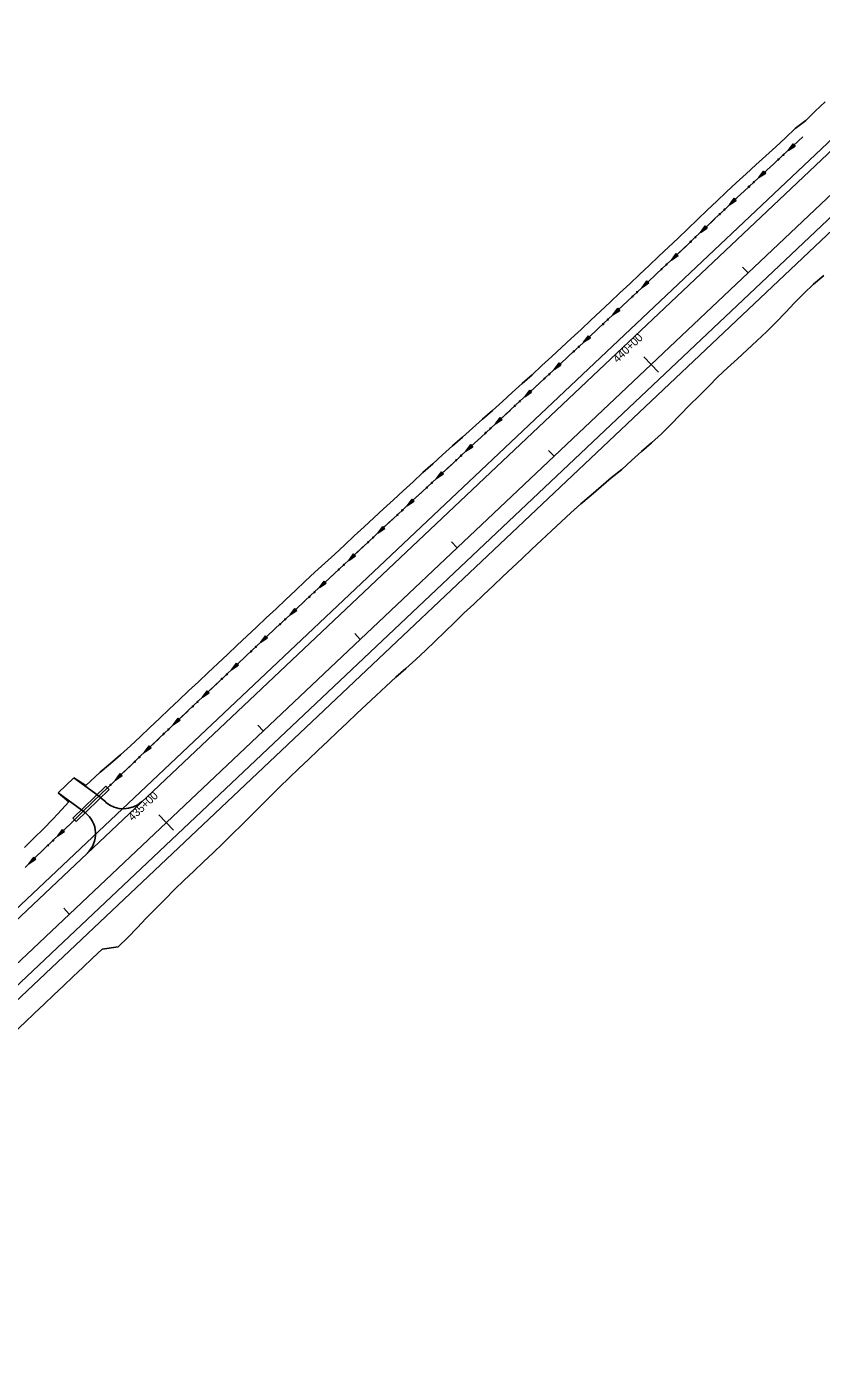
# Model space of a CAD drawing. Extents: x 1375694 to 1433473, y 1931050 to 1967991.
# Drawn here: x 1431005 to 1431601, y 1965367 to 1966371 of the extents above; entities that cross this region are included whole.
import ezdxf

# ---------------------------------------------------------------- set-up
doc = ezdxf.new("R2010")
doc.units = 0
for name, color, linetype in [('62', 7, 'Continuous'), ('R_Drainage', 7, 'Continuous'), ('R_Horz Alg', 7, 'Continuous'), ('R_Horz Alg Annot', 7, 'Continuous'), ('R_Proposed Const Limits', 7, 'Continuous'), ('R_Proposed Road', 7, 'Continuous')]:
    doc.layers.add(name, color=color, linetype=linetype)

msp = doc.modelspace()

# ---------------------------------------------------------------- linework, layer by layer
at = {"layer": '62'}
for p, q in [((1431579.8, 1966283.2), (1431576.1, 1966278.3)), ((1431576.1, 1966278.3), (1431581.2, 1966281.6)), ((1431581.2, 1966281.6), (1431579.8, 1966283.2)), ((1431557.7, 1966262.7), (1431554.1, 1966257.9)), ((1431554.1, 1966257.9), (1431559.2, 1966261.2)), ((1431559.2, 1966261.2), (1431557.7, 1966262.7)), ((1431535.7, 1966242.4), (1431532, 1966237.5)), ((1431532, 1966237.5), (1431537.1, 1966240.8)), ((1431537.1, 1966240.8), (1431535.7, 1966242.4)), ((1431513.9, 1966221.7), (1431510.3, 1966216.8)), ((1431510.3, 1966216.8), (1431515.3, 1966220.1)), ((1431515.3, 1966220.1), (1431513.9, 1966221.7)), ((1431492.1, 1966201), (1431488.5, 1966196.1)), ((1431488.5, 1966196.1), (1431493.6, 1966199.4)), ((1431493.6, 1966199.4), (1431492.1, 1966201)), ((1431470.2, 1966180.4), (1431466.6, 1966175.5)), ((1431466.6, 1966175.5), (1431471.7, 1966178.9)), ((1431471.7, 1966178.9), (1431470.2, 1966180.4)), ((1431448.3, 1966159.9), (1431444.7, 1966155)), ((1431444.7, 1966155), (1431449.8, 1966158.3)), ((1431449.8, 1966158.3), (1431448.3, 1966159.9)), ((1431426.4, 1966139.3), (1431422.7, 1966134.5)), ((1431422.7, 1966134.5), (1431427.8, 1966137.8)), ((1431427.8, 1966137.8), (1431426.4, 1966139.3)), ((1431404.4, 1966118.9), (1431400.7, 1966114)), ((1431400.7, 1966114), (1431405.8, 1966117.3)), ((1431405.8, 1966117.3), (1431404.4, 1966118.9)), ((1431382.4, 1966098.5), (1431378.7, 1966093.6)), ((1431378.7, 1966093.6), (1431383.8, 1966096.9)), ((1431383.8, 1966096.9), (1431382.4, 1966098.5)), ((1431360.3, 1966078.1), (1431356.6, 1966073.2)), ((1431356.6, 1966073.2), (1431361.7, 1966076.5)), ((1431361.7, 1966076.5), (1431360.3, 1966078.1)), ((1431338.2, 1966057.7), (1431334.6, 1966052.8)), ((1431334.6, 1966052.8), (1431339.7, 1966056.1)), ((1431339.7, 1966056.1), (1431338.2, 1966057.7)), ((1431316.2, 1966037.2), (1431312.6, 1966032.4)), ((1431312.6, 1966032.4), (1431317.7, 1966035.7)), ((1431317.7, 1966035.7), (1431316.2, 1966037.2)), ((1431294.2, 1966016.8), (1431290.6, 1966011.9)), ((1431295.7, 1966015.2), (1431294.2, 1966016.8)), ((1431290.6, 1966011.9), (1431295.7, 1966015.2)), ((1431272.3, 1965996.3), (1431268.6, 1965991.4)), ((1431273.7, 1965994.8), (1431272.3, 1965996.3)), ((1431268.6, 1965991.4), (1431273.7, 1965994.8)), ((1431250.3, 1965975.8), (1431246.7, 1965970.9)), ((1431251.8, 1965974.2), (1431250.3, 1965975.8)), ((1431246.7, 1965970.9), (1431251.8, 1965974.2)), ((1431228.3, 1965955.3), (1431224.7, 1965950.5)), ((1431229.8, 1965953.8), (1431228.3, 1965955.3)), ((1431224.7, 1965950.5), (1431229.8, 1965953.8)), ((1431206.3, 1965934.9), (1431202.7, 1965930)), ((1431202.7, 1965930), (1431207.8, 1965933.3)), ((1431207.8, 1965933.3), (1431206.3, 1965934.9)), ((1431184.4, 1965914.3), (1431180.8, 1965909.5)), ((1431180.8, 1965909.5), (1431185.9, 1965912.8)), ((1431185.9, 1965912.8), (1431184.4, 1965914.3)), ((1431162.5, 1965893.8), (1431158.9, 1965888.9)), ((1431158.9, 1965888.9), (1431164, 1965892.2)), ((1431164, 1965892.2), (1431162.5, 1965893.8)), ((1431140.7, 1965873.2), (1431137, 1965868.3)), ((1431137, 1965868.3), (1431142.1, 1965871.6)), ((1431142.1, 1965871.6), (1431140.7, 1965873.2)), ((1431118.9, 1965852.5), (1431115.2, 1965847.6)), ((1431115.2, 1965847.6), (1431120.3, 1965851)), ((1431120.3, 1965851), (1431118.9, 1965852.5)), ((1431097.1, 1965831.8), (1431093.5, 1965826.9)), ((1431093.5, 1965826.9), (1431098.6, 1965830.3)), ((1431098.6, 1965830.3), (1431097.1, 1965831.8)), ((1431075.4, 1965811), (1431071.8, 1965806.1)), ((1431071.8, 1965806.1), (1431076.9, 1965809.5)), ((1431076.9, 1965809.5), (1431075.4, 1965811)), ((1431032.2, 1965769.2), (1431028.7, 1965764.3)), ((1431028.7, 1965764.3), (1431033.7, 1965767.7)), ((1431033.7, 1965767.7), (1431032.2, 1965769.2)), ((1431010.6, 1965748.4), (1431007, 1965743.4)), ((1431007, 1965743.4), (1431012.1, 1965746.8)), ((1431012.1, 1965746.8), (1431010.6, 1965748.4))]:
    msp.add_line(p, q, dxfattribs=at)
for points in [[(1431004.1, 1965740.6), (1431011.3, 1965747.6), (1431018.5, 1965754.5), (1431025.7, 1965761.5), (1431032.9, 1965768.4), (1431040.1, 1965775.4), (1431047.3, 1965782.4), (1431054.4, 1965789.3), (1431061.6, 1965796.3), (1431068.8, 1965803.2), (1431076, 1965810.1), (1431083.3, 1965817.1), (1431090.5, 1965824), (1431097.7, 1965830.9), (1431104.9, 1965837.8), (1431112.2, 1965844.7), (1431119.4, 1965851.6), (1431126.7, 1965858.5), (1431133.9, 1965865.4), (1431141.2, 1965872.2), (1431148.5, 1965879.1), (1431155.7, 1965885.9), (1431163, 1965892.8), (1431170.3, 1965899.7), (1431177.6, 1965906.5), (1431184.9, 1965913.3), (1431192.2, 1965920.2), (1431199.5, 1965927), (1431206.8, 1965933.9), (1431214.1, 1965940.7), (1431221.4, 1965947.5), (1431228.8, 1965954.3), (1431236.1, 1965961.1), (1431243.4, 1965967.9), (1431250.7, 1965974.7), (1431258, 1965981.5), (1431265.3, 1965988.4), (1431272.6, 1965995.2), (1431279.9, 1966002), (1431287.3, 1966008.8), (1431294.6, 1966015.7), (1431301.9, 1966022.5), (1431309.2, 1966029.3), (1431316.5, 1966036.1), (1431323.9, 1966042.9), (1431331.2, 1966049.7), (1431338.5, 1966056.5), (1431345.9, 1966063.3), (1431353.2, 1966070.1), (1431360.5, 1966076.9), (1431367.9, 1966083.7), (1431375.2, 1966090.5), (1431382.6, 1966097.3), (1431389.9, 1966104), (1431397.3, 1966110.8), (1431404.6, 1966117.6), (1431411.9, 1966124.4), (1431419.3, 1966131.2), (1431426.6, 1966138.1), (1431433.9, 1966144.9), (1431441.2, 1966151.7), (1431448.5, 1966158.6), (1431455.8, 1966165.4), (1431463.1, 1966172.2), (1431470.3, 1966179.1), (1431477.6, 1966185.9), (1431484.9, 1966192.8), (1431492.2, 1966199.6), (1431499.5, 1966206.5), (1431506.7, 1966213.4), (1431514, 1966220.3), (1431521.2, 1966227.2), (1431528.5, 1966234.1), (1431535.7, 1966240.9), (1431543.1, 1966247.7), (1431550.4, 1966254.5), (1431557.7, 1966261.3), (1431565.1, 1966268.1), (1431572.4, 1966274.9), (1431579.8, 1966281.7), (1431587.1, 1966288.5)], [(1431587.1, 1966288.5), (1431579.8, 1966281.7), (1431576.1, 1966278.3)], [(1431565.1, 1966268.1), (1431557.7, 1966261.3), (1431554.1, 1966257.9)], [(1431565.1, 1966268.1), (1431565.1, 1966268.1), (1431565.1, 1966268.1)], [(1431543, 1966247.7), (1431535.7, 1966240.9), (1431532, 1966237.5)], [(1431543, 1966247.7), (1431543, 1966247.7)], [(1431521.1, 1966227.1), (1431514, 1966220.3), (1431510.3, 1966216.8)], [(1431521.2, 1966227.1), (1431521.1, 1966227.1)], [(1431499.4, 1966206.4), (1431492.2, 1966199.6), (1431488.5, 1966196.1)], [(1431499.4, 1966206.4), (1431499.4, 1966206.4)], [(1431477.5, 1966185.8), (1431470.3, 1966179.1), (1431466.6, 1966175.5)], [(1431477.5, 1966185.8), (1431477.5, 1966185.8)], [(1431455.6, 1966165.3), (1431448.5, 1966158.6), (1431444.7, 1966155)], [(1431455.6, 1966165.3), (1431455.6, 1966165.3)], [(1431433.7, 1966144.7), (1431426.6, 1966138.1), (1431422.7, 1966134.5)], [(1431433.7, 1966144.7), (1431433.7, 1966144.7)], [(1431411.7, 1966124.2), (1431404.6, 1966117.6), (1431400.7, 1966114)], [(1431411.7, 1966124.3), (1431411.7, 1966124.2)], [(1431389.7, 1966103.8), (1431382.6, 1966097.3), (1431378.7, 1966093.6)], [(1431389.7, 1966103.8), (1431389.7, 1966103.8)], [(1431367.6, 1966083.4), (1431360.5, 1966076.9), (1431356.6, 1966073.2)], [(1431367.6, 1966083.5), (1431367.6, 1966083.4)], [(1431345.6, 1966063), (1431338.5, 1966056.5), (1431334.6, 1966052.8)], [(1431345.6, 1966063.1), (1431345.6, 1966063)], [(1431323.6, 1966042.6), (1431316.5, 1966036.1), (1431312.6, 1966032.4)], [(1431323.6, 1966042.6), (1431323.6, 1966042.6)], [(1431301.5, 1966022.1), (1431294.6, 1966015.7), (1431290.6, 1966011.9)], [(1431301.6, 1966022.2), (1431301.5, 1966022.1)], [(1431279.6, 1966001.7), (1431272.6, 1965995.2), (1431268.6, 1965991.4)], [(1431279.6, 1966001.7), (1431279.6, 1966001.7)], [(1431257.6, 1965981.2), (1431250.7, 1965974.7), (1431246.7, 1965970.9)], [(1431257.6, 1965981.2), (1431257.6, 1965981.2)], [(1431235.7, 1965960.7), (1431228.8, 1965954.3), (1431224.7, 1965950.5)], [(1431235.7, 1965960.7), (1431235.7, 1965960.7)], [(1431213.6, 1965940.2), (1431206.8, 1965933.9), (1431202.7, 1965930)], [(1431213.7, 1965940.3), (1431213.6, 1965940.2)], [(1431191.7, 1965919.7), (1431184.9, 1965913.3), (1431180.8, 1965909.5)], [(1431191.7, 1965919.8), (1431191.7, 1965919.7)], [(1431169.8, 1965899.2), (1431163, 1965892.8), (1431158.9, 1965888.9)], [(1431169.8, 1965899.2), (1431169.8, 1965899.2)], [(1431147.9, 1965878.6), (1431141.2, 1965872.2), (1431137, 1965868.3)], [(1431148, 1965878.6), (1431147.9, 1965878.6)], [(1431126.1, 1965857.9), (1431119.4, 1965851.6), (1431115.2, 1965847.6)], [(1431126.1, 1965858), (1431126.1, 1965857.9)], [(1431104.3, 1965837.2), (1431097.7, 1965830.9), (1431093.5, 1965826.9)], [(1431104.4, 1965837.3), (1431104.3, 1965837.2)], [(1431082.6, 1965816.5), (1431076, 1965810.1), (1431071.8, 1965806.1)], [(1431082.7, 1965816.5), (1431082.6, 1965816.5)], [(1431039.4, 1965774.7), (1431032.9, 1965768.4), (1431028.7, 1965764.3)], [(1431039.4, 1965774.8), (1431039.4, 1965774.7)], [(1431017.8, 1965753.8), (1431011.3, 1965747.6), (1431007, 1965743.4)], [(1431017.9, 1965753.9), (1431017.8, 1965753.8)]]:
    msp.add_lwpolyline(points, dxfattribs=at)
for centre in [(1431568.8, 1966271.5), (1431572.5, 1966274.9), (1431546.7, 1966251.1), (1431550.4, 1966254.5), (1431524.8, 1966230.5), (1431528.4, 1966234), (1431503, 1966209.8), (1431506.7, 1966213.3), (1431481.2, 1966189.2), (1431484.8, 1966192.7), (1431459.3, 1966168.7), (1431462.9, 1966172.1), (1431437.4, 1966148.1), (1431441, 1966151.5), (1431415.4, 1966127.6), (1431419.1, 1966131), (1431393.4, 1966107.2), (1431397.1, 1966110.6), (1431371.3, 1966086.8), (1431375, 1966090.2), (1431349.3, 1966066.4), (1431352.9, 1966069.8), (1431327.3, 1966046), (1431330.9, 1966049.4), (1431305.3, 1966025.5), (1431308.9, 1966029), (1431283.3, 1966005.1), (1431286.9, 1966008.5), (1431265, 1965988), (1431261.3, 1965984.6), (1431243, 1965967.5), (1431239.4, 1965964.1), (1431221, 1965947), (1431217.3, 1965943.6), (1431199, 1965926.6), (1431195.4, 1965923.1), (1431177.1, 1965906), (1431173.5, 1965902.6), (1431155.3, 1965885.4), (1431151.6, 1965882), (1431133.4, 1965864.8), (1431129.8, 1965861.4), (1431108, 1965840.7), (1431111.6, 1965844.1), (1431086.3, 1965819.9), (1431089.9, 1965823.4), (1431068.2, 1965802.6), (1431021.5, 1965757.3), (1431025.1, 1965760.8)]:
    msp.add_circle(centre, 0.375, dxfattribs=at)
at = {"layer": 'R_Drainage'}
for p, q in [((1431064.6, 1965801.6), (1431040, 1965777.7)), ((1431042.4, 1965775.2), (1431067.1, 1965799.1)), ((1431067.1, 1965799.1), (1431064.6, 1965801.6)), ((1431040, 1965777.7), (1431042.4, 1965775.2))]:
    msp.add_line(p, q, dxfattribs=at)
at = {"layer": 'R_Horz Alg'}
msp.add_line((1430431.8, 1965133.5), (1432780.4, 1967352.8), dxfattribs=at)
at = {"layer": 'R_Horz Alg Annot'}
for points in [[(1431541.9, 1966190.7), (1431546, 1966186.4)], [(1431467.8, 1966123.5), (1431478.8, 1966111.9)], [(1431396.5, 1966053.4), (1431400.7, 1966049)], [(1431323.8, 1965984.7), (1431328, 1965980.3)], [(1431251.2, 1965916), (1431255.3, 1965911.6)], [(1431178.5, 1965847.3), (1431182.6, 1965843)], [(1431104.4, 1965780.1), (1431115.4, 1965768.5)], [(1431033.1, 1965710), (1431037.2, 1965705.6)]]:
    msp.add_lwpolyline(points, dxfattribs=at)
at = {"layer": 'R_Proposed Const Limits'}
for p, q in [((1431040.7, 1965807.8), (1431049.8, 1965802.1)), ((1431028.9, 1965796.6), (1431037, 1965789.8))]:
    msp.add_line(p, q, dxfattribs=at)
for points in [[(1431581.4, 1966294.6), (1431589.2, 1966300.8), (1431596.4, 1966307.8), (1431603.7, 1966314.6)], [(1431049.8, 1965802.1), (1431053.1, 1965805.3), (1431060.5, 1965812), (1431068.1, 1965818.6), (1431075.7, 1965825.1), (1431083.1, 1965831.8), (1431090.4, 1965838.7), (1431097.6, 1965845.5), (1431104.9, 1965852.4), (1431112.2, 1965859.3), (1431119.4, 1965866.1), (1431126.7, 1965873), (1431134, 1965879.8), (1431141.3, 1965886.7), (1431148.6, 1965893.5), (1431155.9, 1965900.4), (1431163.1, 1965907.3), (1431170.4, 1965914.1), (1431177.7, 1965920.9), (1431184.9, 1965927.8), (1431192.3, 1965934.6), (1431199.5, 1965941.6), (1431206.9, 1965948.3), (1431214.1, 1965955.2), (1431221.4, 1965962), (1431228.8, 1965968.8), (1431236.2, 1965975.6), (1431243.5, 1965982.4), (1431250.8, 1965989.2), (1431258.2, 1965996), (1431265.5, 1966002.8), (1431272.8, 1966009.6), (1431280.2, 1966016.3), (1431287.5, 1966023.1), (1431294.9, 1966029.9), (1431302.2, 1966036.7), (1431309.7, 1966043.4), (1431317.1, 1966050.1), (1431324.6, 1966056.7), (1431332, 1966063.4), (1431339.4, 1966070.1), (1431346.9, 1966076.7), (1431354.4, 1966083.4), (1431361.9, 1966090.1), (1431369.3, 1966096.7), (1431376.8, 1966103.4), (1431384.2, 1966110.1), (1431391.5, 1966116.9), (1431398.9, 1966123.7), (1431406.2, 1966130.5), (1431413.5, 1966137.3), (1431420.8, 1966144.1), (1431428.1, 1966151), (1431435.4, 1966157.8), (1431442.7, 1966164.6), (1431450, 1966171.5), (1431457.3, 1966178.3), (1431464.6, 1966185.2), (1431471.9, 1966192), (1431479.2, 1966198.9), (1431486.4, 1966205.8), (1431493.7, 1966212.6), (1431500.9, 1966219.5), (1431508.1, 1966226.4), (1431515.4, 1966233.4), (1431522.6, 1966240.3), (1431529.8, 1966247.2), (1431537.2, 1966253.9), (1431544.6, 1966260.7), (1431551.9, 1966267.5), (1431559.3, 1966274.2), (1431566.7, 1966281), (1431574, 1966287.8), (1431581.4, 1966294.6)], [(1431061.9, 1965679.5), (1431074, 1965681.2), (1431081.2, 1965688.2), (1431088.1, 1965695.4), (1431095, 1965702.7), (1431102.1, 1965709.8), (1431109.1, 1965716.9), (1431116.1, 1965724), (1431123.3, 1965731), (1431130.6, 1965737.8), (1431137.8, 1965744.8), (1431145, 1965751.7), (1431152.3, 1965758.5), (1431159.4, 1965765.6), (1431166.5, 1965772.6), (1431173.7, 1965779.6), (1431180.7, 1965786.7), (1431187.8, 1965793.8), (1431194.9, 1965800.8), (1431202, 1965807.9), (1431209.2, 1965814.8), (1431216.5, 1965821.7), (1431223.7, 1965828.5), (1431231, 1965835.4), (1431238.3, 1965842.3), (1431245.5, 1965849.2), (1431252.8, 1965856), (1431260.1, 1965862.9), (1431267.4, 1965869.7), (1431274.7, 1965876.5), (1431282.1, 1965883.2), (1431289.6, 1965889.9), (1431297, 1965896.6), (1431304.3, 1965903.4), (1431311.5, 1965910.4), (1431318.8, 1965917.3), (1431325.9, 1965924.2), (1431333.1, 1965931.2), (1431340.4, 1965938.1), (1431347.6, 1965945), (1431354.9, 1965951.8), (1431362.1, 1965958.7), (1431369.4, 1965965.6), (1431376.7, 1965972.4), (1431384, 1965979.3), (1431391.3, 1965986.1), (1431398.6, 1965993), (1431405.9, 1965999.8), (1431413.3, 1966006.5), (1431420.7, 1966013.2), (1431428.3, 1966019.7), (1431435.8, 1966026.4), (1431443.4, 1966032.9), (1431451.3, 1966039.1), (1431458.7, 1966045.8), (1431466.2, 1966052.5), (1431473.6, 1966059.1), (1431481.1, 1966065.8), (1431488.2, 1966072.9), (1431495.1, 1966080.1), (1431502.2, 1966087.2), (1431509.3, 1966094.2), (1431516.3, 1966101.3), (1431523.4, 1966108.4), (1431530.7, 1966115.2), (1431538.1, 1966122), (1431545.4, 1966128.8), (1431552.7, 1966135.6), (1431560, 1966142.5), (1431567, 1966149.6), (1431574, 1966156.8), (1431580.9, 1966164), (1431587.9, 1966171.1), (1431595.1, 1966178.1), (1431602.7, 1966184.6)], [(1431003.6, 1965755.7), (1431010.8, 1965762.7), (1431018, 1965769.7), (1431024.9, 1965776.9), (1431031.7, 1965784.2), (1431037, 1965789.8)], [(1430982.1, 1965603.8), (1430989.3, 1965610.7), (1430996.6, 1965617.6), (1431003.9, 1965624.4), (1431011.1, 1965631.3), (1431018.4, 1965638.2), (1431025.7, 1965645.1), (1431032.9, 1965651.9), (1431040.2, 1965658.8), (1431047.4, 1965665.7), (1431054.7, 1965672.6), (1431061.9, 1965679.5)]]:
    msp.add_lwpolyline(points, dxfattribs=at)
at = {"layer": 'R_Proposed Road'}
for p, q in [((1430411.1, 1965155.3), (1432759.8, 1967374.6)), ((1430415.3, 1965150.9), (1432763.9, 1967370.2)), ((1430440, 1965124.7), (1432788.7, 1967344.1)), ((1430445.5, 1965118.9), (1432794.2, 1967338.3)), ((1431028.9, 1965796.6), (1431040.7, 1965807.8)), ((1431040.7, 1965807.8), (1431056.1, 1965796.6)), ((1431028.9, 1965796.6), (1431046.6, 1965783.7))]:
    msp.add_line(p, q, dxfattribs=at)
for centre, radius, start, end in [((1430992.4, 1965709.4), 108, 48.0635, 53.8627), ((1431077.9, 1965804.6), 20, 228.0635, 313.3781), ((1430992.4, 1965709.4), 92, 51.728, 53.8627), ((1431037, 1965765.9), 20, 313.3781, 51.728)]:
    msp.add_arc(centre, radius, start, end, dxfattribs=at)

# ---------------------------------------------------------------- texts
at = {"layer": 'R_Horz Alg Annot'}
for s, p in [('440+00', (1431448.1, 1966118.7)), ('435+00', (1431084.7, 1965775.2))]:
    msp.add_text(s, height=6, rotation=43.3781, dxfattribs=at).set_placement(p)

doc.saveas('drawing.dxf')
